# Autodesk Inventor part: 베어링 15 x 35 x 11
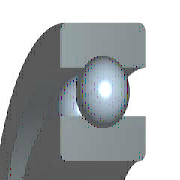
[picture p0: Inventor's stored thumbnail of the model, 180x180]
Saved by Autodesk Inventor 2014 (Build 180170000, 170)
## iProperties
Created: 2012-02
Part Number: 베어링 15 x 35 x 11
Material: 강철, 연강
Description: 깊은 그루브 볼 베어링
Document SubType Name: Modeling
Standard: KS B 2023
Designer: mduedu
Standards Organization: KS
Language: ko-KR
Size Designation: 6202 - 15 x 35 x 11
Categories: <MemberInstance><Categories><Category DisplayName="샤프트 부품" InternalName="7f7aeb1f-a693-4053-b835-cee3144e0d98" Mnemonic="SHFT"><Category DisplayName="베어링" Inter
Density: 1 g/cm^3
Appearance: Steel
IsCustomPart: 1
Author: mduedu
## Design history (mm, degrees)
sketch "스케치" dims "d0" = 5.2 (= -0.26 x WD + 0.26 x BD)
  geometry: L1 (2.9, 12.5)-(8.1, 12.5); L2 (5.5, 12.5)-(5.5, 9.9); L3 (5.5, 12.5)-(5.5, 15.1); L4 (3.568, 10.76)-(0, 10.76); L5 (0, 7.5)-(11, 7.5); L6 (3.568, 14.24)-(0, 14.24); L7 (0, 17.5)-(11, 17.5); L8 (11, 7.5)-(11, 10.76); L9 (7.432, 10.76)-(11, 10.76); L10 (7.432, 14.24)-(11, 14.24); L11 (11, 17.5)-(11, 14.24); L12 (-1.4, 0)-(8.4, 0) reference; L13 (0, -0.3)-(0, 5.3) reference
  constraints: 22 end point, 4 point on line, 2 collinear, 2 perpendicular, 2 symmetric about line, 1 midpoint, 1 parallel, 14 other
  dimensions: "d9" = 15 diameter of L5 L12 (= WD); "d11" = 35 diameter of L7 L12 (= BD); "d12" = 11 distance between parallel lines of L8 L13 (= KB); "d13" = 21.52 diameter of L9 L12 (= 0.326 x BD + 0.674 x WD)
revolve "본체" stored, may be unused: angle "d6" = 90 deg
revolve "볼" stored, may be unused: angle "d7" = 90 deg
pattern_circular "IDS_ARRAYBALL[SIMPL:T]" dims angle "d3" = 360 deg
body "Solid1"
fillet "모깎기1" dims "d1" = 0.6 (= KRS)
other parameters: "WD" = 15 [user parameter; used in 5 equation terms], "BD" = 35 [user parameter; used in 5 equation terms], "KB" = 11 [user parameter; used in 1 equation term], "KRS" = 0.6 [user parameter; used in 1 equation term], "d4" = 0, "d5" = 0, "d8" = 0, "d14" = 0, "d15" = 0, "BBA" = 0 [user parameter], "BC0" = 3750000 [user parameter], "BC" = 7800000 [user parameter], "BR" = 17.5 (= 0.5 x BD) [user parameter], "WR" = 7.5 (= 0.5 x WD) [user parameter]
